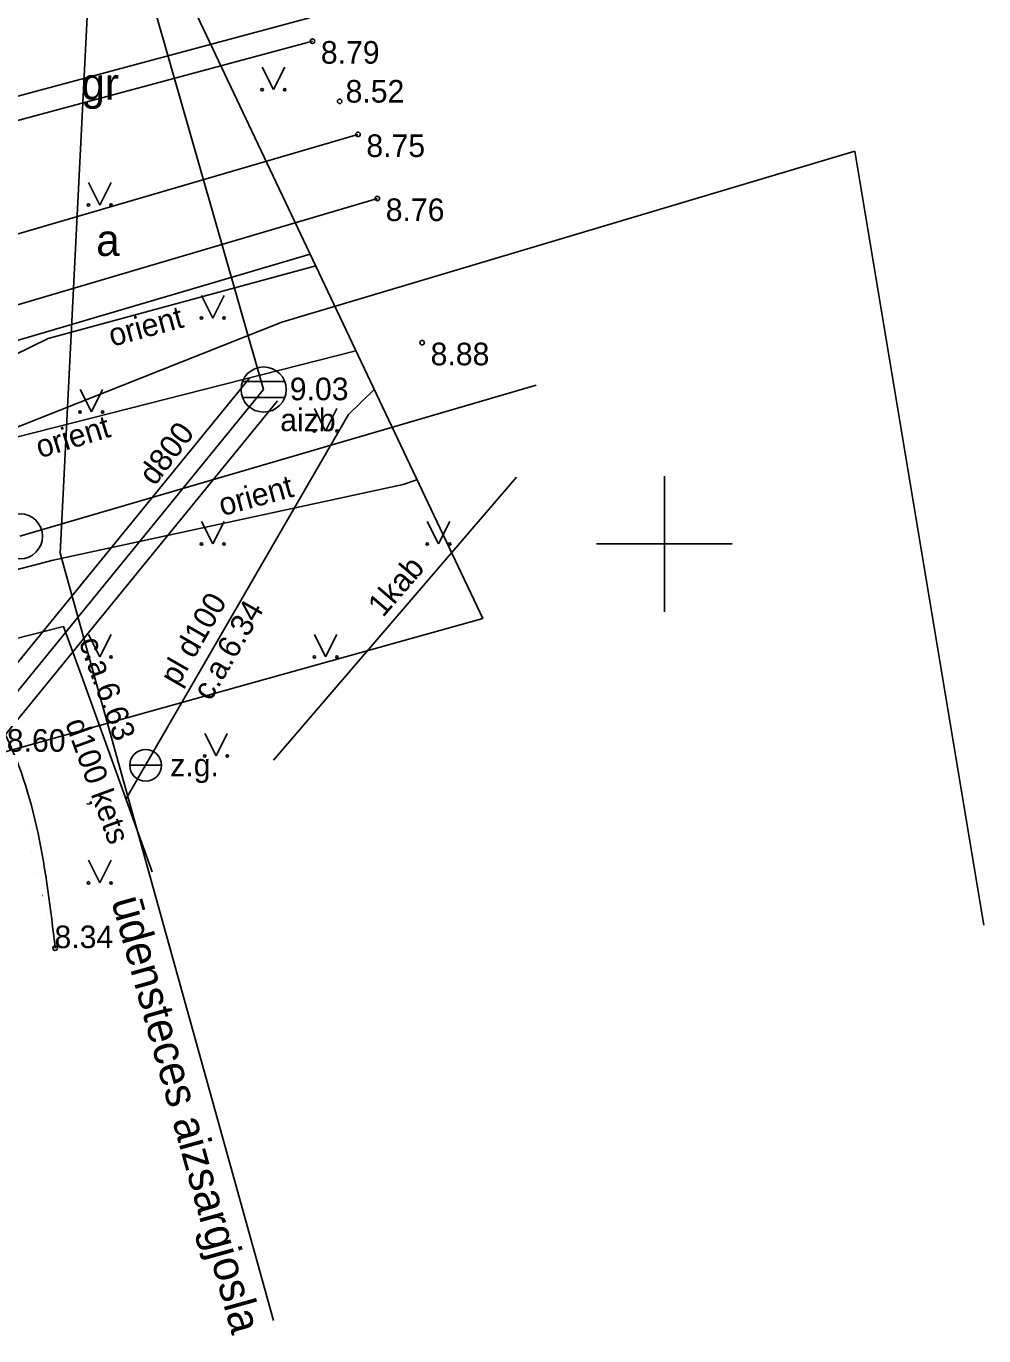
# Model space of a CAD drawing. Extents: x 496078 to 496285, y 304225 to 304369.
# Drawn here: x 496185.87 to 496207.07, y 304282.48 to 304311.46 of the extents above; entities that cross this region are included whole.
import ezdxf

# ---------------------------------------------------------------- set-up
doc = ezdxf.new("R2010")
doc.units = 0
for name, color, linetype in [('APGR_AIZS_####_####_#', 7, 'Continuous'), ('APGR_AIZS_####_TKST_#', 7, 'Continuous'), ('APGR_ELEM_####_####_#', 7, 'Continuous'), ('APGR_SARK_####_####_#', 7, 'Continuous'), ('APGS_VADP_ZSPR_####_#', 7, 'Continuous'), ('CELI_CAPM_####_####_#', 7, 'Continuous'), ('CELI_CMAL_####_####_#', 7, 'Continuous'), ('CELI_CSEG_####_TKST_#', 7, 'Continuous'), ('GEOD_ELEM_####_####_#', 7, 'Continuous'), ('Level 21', 7, 'Continuous'), ('Level 24', 7, 'Continuous'), ('LKAN_ELEM_####_####_#', 7, 'Continuous'), ('LKAN_ELEM_PAST_TKST_#', 7, 'Continuous'), ('LKAN_VADP_PAST_####_#', 7, 'Continuous'), ('LKAN_VADP_PAST_KONT_#', 7, 'Continuous'), ('LKAN_VADP_PAST_TKST_#', 7, 'Continuous'), ('RAMI_UZMR_####_####_#', 7, 'Continuous'), ('RELJ_AATZ_####_TKST_#', 7, 'Continuous'), ('RELJ_ELEM_####_####_#', 7, 'Continuous'), ('RELJ_NOGA_####_####_#', 7, 'Continuous'), ('SAKT_VADP_KABE_####_#', 7, 'Continuous'), ('SAKT_VADP_KABE_TKST_#', 7, 'Continuous'), ('SAKT_VADP_NEDR_####_#', 7, 'Continuous'), ('SAKT_VADP_NEDR_TKST_#', 7, 'Continuous'), ('SAKT_VADV_PKAB_####_#', 7, 'Continuous'), ('SAKT_VADV_PKAB_TKST_#', 7, 'Continuous'), ('TERT_ELEM_####_####_#', 7, 'Continuous'), ('UDTK_ELEM_####_####_#', 7, 'Continuous'), ('UDTK_ELEM_####_TKST_#', 7, 'Continuous'), ('UDTK_VADP_UDEN_####_#', 7, 'Continuous'), ('UDTK_VADP_UDEN_####_I', 7, 'Continuous'), ('UDTK_VADP_UDEN_TKST_#', 7, 'Continuous'), ('UDTK_VADP_UDEN_TKST_I', 7, 'Continuous')]:
    doc.layers.add(name, color=color, linetype=linetype)

msp = doc.modelspace()

# ---------------------------------------------------------------- linework, layer by layer
at = {"layer": 'APGR_AIZS_####_####_#'}
msp.add_line((496188.252, 304332.153), (496186.624, 304299.798), dxfattribs=at)
msp.add_lwpolyline([(496186.624, 304299.798), (496191.348, 304282.817)], dxfattribs=at)
at = {"layer": 'APGR_ELEM_####_####_#'}
msp.add_circle((496185.73, 304300.17), 0.5, dxfattribs=at)
at = {"layer": 'APGR_SARK_####_####_#'}
msp.add_line((496185.729, 304300.172), (496197.161, 304303.516), dxfattribs=at)
at = {"layer": 'APGS_VADP_ZSPR_####_#'}
msp.add_line((496192.158, 304306.411), (496183.894, 304303.985), dxfattribs=at)
at = {"layer": 'CELI_CAPM_####_####_#'}
for points in [[(496182.479, 304305.927), (496193.216, 304309.063)], [(496182.974, 304304.495), (496193.645, 304307.646)]]:
    msp.add_lwpolyline(points, dxfattribs=at)
at = {"layer": 'CELI_CMAL_####_####_#'}
for points in [[(496169.864, 304303.13), (496168.559, 304302.187), (496166.548, 304301.675), (496165.812, 304304.226), (496169.3, 304305.578), (496176.443, 304307.431), (496192.141, 304311.641)], [(496166.677, 304301.708), (496169.783, 304304.413), (496176.513, 304306.904), (496192.208, 304311.128)]]:
    msp.add_lwpolyline(points, dxfattribs=at)
at = {"layer": 'GEOD_ELEM_####_####_#'}
for p, q in [((496200, 304301.5), (496200, 304300)), ((496198.5, 304300), (496200, 304300)), ((496200, 304300), (496200, 304298.5)), ((496200, 304300), (496201.5, 304300))]:
    msp.add_line(p, q, dxfattribs=at)
at = {"layer": 'Level 21'}
for points in [[(496204.216, 304308.693), (496191.531, 304304.907)], [(496191.531, 304304.907), (496176.843, 304299.089)]]:
    msp.add_lwpolyline(points, dxfattribs=at)
at = {"layer": 'Level 24'}
msp.add_lwpolyline([(496207.074, 304291.566), (496204.216, 304308.693)], dxfattribs=at)
at = {"layer": 'LKAN_ELEM_####_####_#'}
for p, q in [((496190.659, 304303.593), (496191.595, 304303.593)), ((496190.659, 304303.243), (496191.595, 304303.243))]:
    msp.add_line(p, q, dxfattribs=at)
msp.add_circle((496191.127, 304303.418), 0.5, dxfattribs=at)
at = {"layer": 'LKAN_VADP_PAST_####_#'}
for p in [(496188.241, 304313.49), (496182.922, 304293.368)]:
    msp.add_line(p, (496191.127, 304303.418), dxfattribs=at)
at = {"layer": 'LKAN_VADP_PAST_KONT_#'}
for p, q in [((496182.708, 304293.738), (496190.817, 304303.671)), ((496183.232, 304293.115), (496191.437, 304303.165))]:
    msp.add_line(p, q, dxfattribs=at)
at = {"layer": 'RAMI_UZMR_####_####_#'}
for p, q in [((496195.979, 304298.352), (496181.881, 304328.088)), ((496139.922, 304282.712), (496195.979, 304298.352))]:
    msp.add_line(p, q, dxfattribs=at)
at = {"layer": 'RELJ_ELEM_####_####_#'}
for centre in [(496192.208, 304311.128), (496192.811, 304309.794), (496193.216, 304309.063), (496193.645, 304307.646), (496194.639, 304304.454), (496186.512, 304291.057)]:
    msp.add_circle(centre, 0.05, dxfattribs=at)
at = {"layer": 'RELJ_NOGA_####_####_#'}
for p, q in [((496185.872, 304293.679), (496185.871, 304293.679)), ((496185.99, 304293.194), (496185.989, 304293.193)), ((496186.109, 304292.708), (496186.109, 304292.708)), ((496186.227, 304292.222), (496186.226, 304292.222)), ((496186.346, 304291.736), (496186.346, 304291.736)), ((496186.465, 304291.251), (496186.464, 304291.251))]:
    msp.add_line(p, q, dxfattribs=at)
msp.add_spline([(496182.401, 304303.286), (496182.758, 304300.034), (496185.315, 304295.959), (496186.512, 304291.057)], degree=3, dxfattribs=at)
at = {"layer": 'SAKT_VADP_KABE_####_#'}
msp.add_lwpolyline([(496167.053, 304289.039), (496173.605, 304298.868), (496174.688, 304299.362), (496178.745, 304300.248), (496183.885, 304301.628), (496183.489, 304302.815), (496183.729, 304303.26), (496186.359, 304304.549), (496192.281, 304306.153)], dxfattribs=at)
at = {"layer": 'SAKT_VADP_NEDR_####_#'}
for p, q in [((496193.172, 304304.273), (496182.035, 304301.441)), ((496194.216, 304301.319), (496194.523, 304301.423)), ((496186.466, 304299.643), (496194.216, 304301.319)), ((496180.709, 304298.148), (496186.466, 304299.643))]:
    msp.add_line(p, q, dxfattribs=at)
at = {"layer": 'SAKT_VADV_PKAB_####_#'}
msp.add_line((496191.342, 304295.213), (496196.726, 304301.476), dxfattribs=at)
at = {"layer": 'TERT_ELEM_####_####_#'}
for p, q in [((496191.097, 304310.553), (496191.347, 304310.053)), ((496191.347, 304310.053), (496191.597, 304310.553)), ((496187.25, 304308), (496187.5, 304307.5)), ((496187.5, 304307.5), (496187.75, 304308)), ((496189.75, 304305.5), (496190, 304305)), ((496190, 304305), (496190.25, 304305.5)), ((496187.062, 304303.422), (496187.312, 304302.922)), ((496187.312, 304302.922), (496187.562, 304303.422)), ((496192.25, 304303), (496192.5, 304302.5)), ((496192.5, 304302.5), (496192.75, 304303)), ((496189.75, 304300.5), (496190, 304300)), ((496190, 304300), (496190.25, 304300.5)), ((496194.75, 304300.5), (496195, 304300)), ((496195, 304300), (496195.25, 304300.5)), ((496187.25, 304298), (496187.5, 304297.5)), ((496187.5, 304297.5), (496187.75, 304298)), ((496192.25, 304298), (496192.5, 304297.5)), ((496192.5, 304297.5), (496192.75, 304298)), ((496189.823, 304295.809), (496190.073, 304295.309)), ((496190.073, 304295.309), (496190.323, 304295.809)), ((496187.25, 304293), (496187.5, 304292.5)), ((496187.5, 304292.5), (496187.75, 304293))]:
    msp.add_line(p, q, dxfattribs=at)
for centre, radius in [((496191.096, 304310.052), 0.028), ((496191.596, 304310.052), 0.0263), ((496187.25, 304307.5), 0.028), ((496187.75, 304307.5), 0.0263), ((496189.75, 304305), 0.028), ((496190.25, 304305), 0.0263), ((496187.061, 304302.922), 0.028), ((496187.561, 304302.922), 0.0263), ((496192.25, 304302.5), 0.028), ((496192.75, 304302.5), 0.0263), ((496189.75, 304300), 0.028), ((496190.25, 304300), 0.0263), ((496194.75, 304300), 0.028), ((496195.25, 304300), 0.0263), ((496187.25, 304297.5), 0.028), ((496187.75, 304297.5), 0.0263), ((496192.25, 304297.5), 0.028), ((496192.75, 304297.5), 0.0263), ((496189.823, 304295.308), 0.028), ((496190.323, 304295.308), 0.0263), ((496187.25, 304292.5), 0.028), ((496187.75, 304292.5), 0.0263)]:
    msp.add_circle(centre, radius, dxfattribs=at)
at = {"layer": 'UDTK_ELEM_####_####_#'}
msp.add_line((496188.161, 304295.103), (496188.863, 304295.103), dxfattribs=at)
msp.add_circle((496188.512, 304295.103), 0.351, dxfattribs=at)
at = {"layer": 'UDTK_VADP_UDEN_####_#'}
for p, q in [((496179.718, 304296.4), (496186.699, 304298.174)), ((496186.699, 304298.174), (496187.087, 304297.102))]:
    msp.add_line(p, q, dxfattribs=at)
msp.add_lwpolyline([(496188.66, 304292.749), (496187.862, 304294.956), (496187.087, 304297.102)], dxfattribs=at)
at = {"layer": 'UDTK_VADP_UDEN_####_I'}
msp.add_lwpolyline([(496193.577, 304303.418), (496193.007, 304302.864), (496188.512, 304295.103), (496188.079, 304294.356)], dxfattribs=at)

# ---------------------------------------------------------------- texts
at = {"layer": 'APGR_AIZS_####_TKST_#'}
msp.add_text('ūdensteces aizsargjosla', height=0.7, rotation=285.5452, dxfattribs=at).set_placement((496187.751, 304292.103))
at = {"layer": 'CELI_CSEG_####_TKST_#'}
for s, p in [('gr', (496187.091, 304309.833)), ('a', (496187.419, 304306.375))]:
    msp.add_text(s, height=0.7, dxfattribs=at).set_placement(p)
at = {"layer": 'LKAN_ELEM_PAST_TKST_#'}
for s, p in [('9.03', (496191.706, 304303.181)), ('aizb', (496191.494, 304302.496))]:
    msp.add_text(s, height=0.5, dxfattribs=at).set_placement(p)
at = {"layer": 'LKAN_VADP_PAST_TKST_#'}
msp.add_text('d800', height=0.5, rotation=52.8283, dxfattribs=at).set_placement((496188.718, 304301.267))
at = {"layer": 'RELJ_AATZ_####_TKST_#'}
for s, p in [(' 8.79', (496192.208, 304310.628)), (' 8.52', (496192.756, 304309.767)), (' 8.75', (496193.216, 304308.563)), (' 8.76', (496193.645, 304307.146)), (' 8.88', (496194.639, 304303.954)), (' 8.60', (496185.254, 304295.403)), (' 8.34', (496186.31, 304291.057))]:
    msp.add_text(s, height=0.5, dxfattribs=at).set_placement(p)
at = {"layer": 'SAKT_VADP_KABE_TKST_#'}
msp.add_text('orient ', height=0.5, rotation=15.1601, dxfattribs=at).set_placement((496187.772, 304304.363))
at = {"layer": 'SAKT_VADP_NEDR_TKST_#'}
for rotation, p in [(16.9376, (496186.172, 304301.893)), (15.3503, (496190.211, 304300.613))]:
    msp.add_text('orient', height=0.5, rotation=rotation, dxfattribs=at).set_placement(p)
at = {"layer": 'SAKT_VADV_PKAB_TKST_#'}
msp.add_text('1kab', height=0.5, rotation=49.3145, dxfattribs=at).set_placement((496193.77, 304298.357))
at = {"layer": 'UDTK_ELEM_####_TKST_#'}
msp.add_text('z.g.', height=0.5, dxfattribs=at).set_placement((496189.059, 304294.859))
at = {"layer": 'UDTK_VADP_UDEN_TKST_#'}
for s, p in [('c.a.6.63', (496187.028, 304297.839)), ('d100 ķets', (496186.726, 304296.041))]:
    msp.add_text(s, height=0.5, rotation=289.8729, dxfattribs=at).set_placement(p)
at = {"layer": 'UDTK_VADP_UDEN_TKST_I'}
for s, p in [('pl d100', (496189.229, 304296.831)), ('c.a.6.34', (496189.954, 304296.503))]:
    msp.add_text(s, height=0.5, rotation=59.9215, dxfattribs=at).set_placement(p)

doc.saveas('drawing.dxf')
